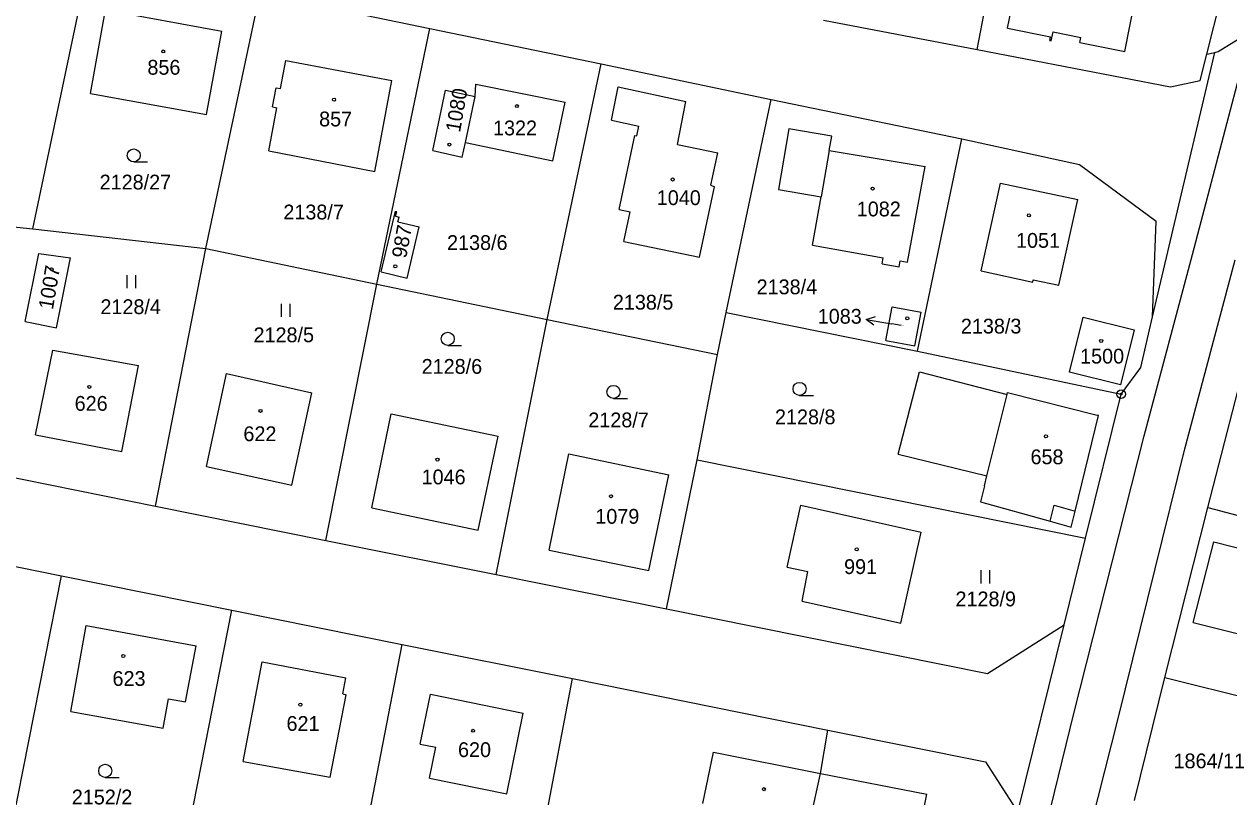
# Model space of a CAD drawing. Extents: x -763205 to -760228, y -1155311 to -1152844.
# Drawn here: x -762054.7 to -761916.2, y -1154656.3 to -1154567.5 of the extents above; entities that cross this region are included whole.
import ezdxf

# ---------------------------------------------------------------- set-up
doc = ezdxf.new("R2010")
doc.units = 0
for name, color, linetype in [('Vrstva 1', 7, 'Continuous'), ('Vrstva 16', 7, 'Continuous'), ('Vrstva 18', 7, 'Continuous'), ('Vrstva 19', 7, 'Continuous'), ('Vrstva 24', 7, 'Continuous'), ('Vrstva 25', 7, 'Continuous'), ('Vrstva 4', 7, 'Continuous')]:
    doc.layers.add(name, color=color, linetype=linetype)

msp = doc.modelspace()

# ---------------------------------------------------------------- linework, layer by layer
at = {"layer": 'Vrstva 1'}
for p, q in [((-761945.16, -1154570.4), (-761942.15, -1154554.69)), ((-761941.67, -1154567.93), (-761939.79, -1154558.64)), ((-761918.77, -1154570.92), (-761915.94, -1154559.73)), ((-762053.67, -1154591.01), (-762047.13, -1154559.9)), ((-761928.21, -1154570.62), (-761926.33, -1154561.22)), ((-762033.79, -1154593.27), (-762027.58, -1154563.92)), ((-762027.58, -1154563.92), (-762008.04, -1154567.96)), ((-762047.05, -1154575.43), (-762045.3, -1154565.83)), ((-762045.3, -1154565.83), (-762031.95, -1154568.28)), ((-762014.14, -1154597.34), (-762008.04, -1154567.96)), ((-762008.04, -1154567.96), (-761988.37, -1154572.04)), ((-761962.8, -1154567), (-761945.16, -1154570.4)), ((-761941.67, -1154567.93), (-761936.72, -1154568.92)), ((-762033.72, -1154577.84), (-762031.95, -1154568.28)), ((-761936.81, -1154569.36), (-761936.72, -1154568.92)), ((-761936.81, -1154569.36), (-761936.64, -1154569.4)), ((-761936.64, -1154569.4), (-761936.44, -1154568.36)), ((-761936.44, -1154568.36), (-761933.24, -1154569)), ((-761933.36, -1154569.59), (-761933.24, -1154569)), ((-761917.45, -1154570.63), (-761913.66, -1154568.26)), ((-761945.16, -1154570.4), (-761922.93, -1154574.67)), ((-761933.36, -1154569.59), (-761928.21, -1154570.62)), ((-761925, -1154601.1), (-761917.85, -1154570.72)), ((-761919.53, -1154573.93), (-761918.77, -1154570.92)), ((-761918.77, -1154570.92), (-761917.85, -1154570.72)), ((-761917.85, -1154570.72), (-761917.45, -1154570.63)), ((-762025.21, -1154574.88), (-762024.6, -1154571.66)), ((-762024.6, -1154571.66), (-762012.4, -1154573.95)), ((-761994.56, -1154601.41), (-761988.37, -1154572.04)), ((-761988.37, -1154572.04), (-761968.83, -1154576.12)), ((-762026.12, -1154576.98), (-762025.71, -1154574.79)), ((-762025.71, -1154574.79), (-762025.21, -1154574.88)), ((-762014.37, -1154584.4), (-762012.4, -1154573.95)), ((-762007.71, -1154582), (-762006.25, -1154575.05)), ((-762006.25, -1154575.05), (-762002.86, -1154575.8)), ((-762002.86, -1154575.8), (-762002.75, -1154574.38)), ((-762002.75, -1154574.38), (-761992.52, -1154576.43)), ((-761987.19, -1154578.49), (-761986.4, -1154574.67)), ((-761986.4, -1154574.67), (-761978.65, -1154576.36)), ((-761922.93, -1154574.67), (-761919.53, -1154573.93)), ((-762047.05, -1154575.43), (-762033.72, -1154577.84)), ((-762003.97, -1154581.06), (-762002.86, -1154575.8)), ((-761993.91, -1154583.16), (-761992.52, -1154576.43)), ((-761979.58, -1154581.31), (-761978.65, -1154576.36)), ((-761973.99, -1154600.62), (-761968.83, -1154576.12)), ((-761968.83, -1154576.12), (-761946.93, -1154580.64)), ((-762026.55, -1154582.03), (-762025.62, -1154577.07)), ((-762026.12, -1154576.98), (-762025.62, -1154577.07)), ((-761987.19, -1154578.49), (-761984.02, -1154579.18)), ((-761984.26, -1154580.32), (-761984.02, -1154579.18)), ((-761986.3, -1154588.77), (-761984.5, -1154580.27)), ((-761984.5, -1154580.27), (-761984.26, -1154580.32)), ((-761966.81, -1154579.49), (-761967.99, -1154586.49)), ((-761961.87, -1154580.33), (-761966.81, -1154579.49)), ((-761962.15, -1154581.99), (-761961.87, -1154580.33)), ((-761952.02, -1154605.04), (-761946.93, -1154580.64)), ((-761946.93, -1154580.64), (-761933.4, -1154583.6)), ((-762007.71, -1154582), (-762004.32, -1154582.75)), ((-762004.32, -1154582.75), (-762003.97, -1154581.06)), ((-762003.97, -1154581.06), (-761993.91, -1154583.16)), ((-761979.58, -1154581.31), (-761974.96, -1154582.24)), ((-761962.15, -1154581.99), (-761951.14, -1154583.83)), ((-762026.55, -1154582.03), (-762014.37, -1154584.4)), ((-761975.75, -1154585.99), (-761974.96, -1154582.24)), ((-761953.16, -1154594.83), (-761951.14, -1154583.83)), ((-761933.4, -1154583.6), (-761924.59, -1154590.1)), ((-761977.07, -1154594.24), (-761975.36, -1154586.15)), ((-761975.75, -1154585.99), (-761975.36, -1154586.15)), ((-761944.7, -1154595.82), (-761942.47, -1154585.73)), ((-761942.47, -1154585.73), (-761933.6, -1154587.63)), ((-761967.99, -1154586.49), (-761963.1, -1154587.31)), ((-761964.09, -1154592.88), (-761963.1, -1154587.31)), ((-761986.3, -1154588.77), (-761985.04, -1154589.04)), ((-761935.78, -1154597.48), (-761933.6, -1154587.63)), ((-762013.65, -1154595.93), (-762012.01, -1154588.97)), ((-762012.01, -1154588.97), (-762011.86, -1154589)), ((-762011.99, -1154589.54), (-762011.86, -1154589)), ((-762011.99, -1154589.54), (-762011.58, -1154589.64)), ((-762011.71, -1154590.18), (-762011.58, -1154589.64)), ((-762011.71, -1154590.18), (-762009.28, -1154590.75)), ((-761985.76, -1154592.44), (-761985.04, -1154589.04)), ((-761925, -1154601.1), (-761924.59, -1154590.1)), ((-762059.87, -1154590.35), (-762053.67, -1154591.01)), ((-762053.67, -1154591.01), (-762033.79, -1154593.27)), ((-762010.65, -1154596.66), (-762009.28, -1154590.75)), ((-761985.76, -1154592.44), (-761977.07, -1154594.24)), ((-761964.09, -1154592.88), (-761955.96, -1154594.32)), ((-762054.56, -1154601.65), (-762052.99, -1154593.83)), ((-762052.99, -1154593.83), (-762049.33, -1154594.31)), ((-762050.95, -1154602.38), (-762049.33, -1154594.31)), ((-762039.58, -1154622.85), (-762033.79, -1154593.27)), ((-762033.79, -1154593.27), (-762014.14, -1154597.34)), ((-761956.08, -1154595.02), (-761955.96, -1154594.32)), ((-761956.08, -1154595.02), (-761954.12, -1154595.37)), ((-761954.12, -1154595.37), (-761954, -1154594.67)), ((-761954, -1154594.67), (-761953.16, -1154594.83)), ((-761944.7, -1154595.82), (-761938.78, -1154597.12)), ((-762013.65, -1154595.93), (-762010.65, -1154596.66)), ((-761938.78, -1154597.12), (-761938.72, -1154596.84)), ((-761938.72, -1154596.84), (-761935.78, -1154597.48)), ((-762020.01, -1154626.79), (-762014.14, -1154597.34)), ((-762014.14, -1154597.34), (-761994.56, -1154601.41)), ((-761955.65, -1154603.83), (-761954.94, -1154599.94)), ((-761954.94, -1154599.94), (-761951.6, -1154600.55)), ((-761974.99, -1154605.42), (-761973.99, -1154600.62)), ((-761973.99, -1154600.62), (-761952.02, -1154605.04)), ((-761952.31, -1154604.44), (-761951.6, -1154600.55)), ((-761934.54, -1154607.46), (-761933, -1154601.16)), ((-761933, -1154601.16), (-761927.12, -1154602.61)), ((-761926.37, -1154606.94), (-761925, -1154601.1)), ((-762054.56, -1154601.65), (-762050.95, -1154602.38)), ((-762000.43, -1154630.73), (-761994.56, -1154601.41)), ((-761994.56, -1154601.41), (-761974.99, -1154605.42)), ((-761927.12, -1154602.61), (-761928.7, -1154608.93)), ((-761955.65, -1154603.83), (-761952.31, -1154604.44)), ((-762053.35, -1154614.66), (-762051.36, -1154604.93)), ((-762051.36, -1154604.93), (-762041.51, -1154606.69)), ((-761977.33, -1154617.54), (-761974.99, -1154605.42)), ((-761952.02, -1154605.04), (-761928.62, -1154609.98)), ((-762043.44, -1154616.56), (-762041.51, -1154606.69)), ((-761928.62, -1154609.98), (-761926.37, -1154606.94)), ((-762033.71, -1154618.29), (-762031.41, -1154607.61)), ((-762031.41, -1154607.61), (-762021.6, -1154609.82)), ((-761954.23, -1154616.89), (-761951.77, -1154607.41)), ((-761951.77, -1154607.41), (-761941.72, -1154610.01)), ((-761928.7, -1154608.93), (-761934.54, -1154607.46)), ((-761918.67, -1154623.02), (-761915.17, -1154609.49)), ((-762023.9, -1154620.43), (-762021.6, -1154609.82)), ((-761941.72, -1154610.01), (-761941.67, -1154609.8)), ((-761941.67, -1154609.8), (-761931.37, -1154612.39)), ((-761932.71, -1154626.54), (-761928.62, -1154609.98)), ((-762014.7, -1154623.04), (-762012.49, -1154612.26)), ((-762012.49, -1154612.26), (-762000.2, -1154614.83)), ((-761933.9, -1154623.42), (-761931.2, -1154612.43)), ((-761931.2, -1154612.43), (-761931.37, -1154612.39)), ((-762053.35, -1154614.66), (-762043.44, -1154616.56)), ((-762002.48, -1154625.63), (-762000.2, -1154614.83)), ((-761994.33, -1154627.92), (-761992.08, -1154616.86)), ((-761992.08, -1154616.86), (-761980.6, -1154619.25)), ((-761980.86, -1154634.67), (-761977.33, -1154617.54)), ((-761977.33, -1154617.54), (-761932.71, -1154626.54)), ((-761954.23, -1154616.89), (-761944.04, -1154619.39)), ((-762059.16, -1154618.91), (-762039.58, -1154622.85)), ((-762033.71, -1154618.29), (-762023.9, -1154620.43)), ((-761982.89, -1154630.25), (-761980.6, -1154619.25)), ((-761944.32, -1154620.51), (-761944.04, -1154619.39)), ((-761944.32, -1154620.51), (-761944.77, -1154622.35)), ((-762039.58, -1154622.85), (-762020.01, -1154626.79)), ((-762014.7, -1154623.04), (-762002.48, -1154625.63)), ((-761967.01, -1154629.85), (-761965.41, -1154622.75)), ((-761965.41, -1154622.75), (-761951.59, -1154625.85)), ((-761944.77, -1154622.35), (-761936.77, -1154624.6)), ((-761934.36, -1154625.27), (-761933.9, -1154623.42)), ((-761923.59, -1154642.54), (-761918.67, -1154623.02)), ((-761918.67, -1154623.02), (-761888.02, -1154630.97)), ((-761936.77, -1154624.6), (-761934.36, -1154625.27)), ((-761953.92, -1154636.32), (-761951.59, -1154625.85)), ((-762020.01, -1154626.79), (-762000.43, -1154630.73)), ((-761935.17, -1154636.49), (-761932.71, -1154626.54)), ((-761920.36, -1154636.24), (-761917.96, -1154626.94)), ((-761917.96, -1154626.94), (-761907.11, -1154629.74)), ((-761994.33, -1154627.92), (-761982.89, -1154630.25)), ((-762058.73, -1154629.19), (-762050.39, -1154630.87)), ((-761967.01, -1154629.85), (-761964.61, -1154630.38)), ((-761965.26, -1154633.79), (-761964.61, -1154630.38)), ((-762056.56, -1154662.09), (-762050.39, -1154630.87)), ((-762050.39, -1154630.87), (-762030.82, -1154634.81)), ((-762000.43, -1154630.73), (-761980.86, -1154634.67)), ((-761965.26, -1154633.79), (-761953.92, -1154636.32)), ((-762036.89, -1154665.87), (-762030.82, -1154634.81)), ((-762030.82, -1154634.81), (-762011.24, -1154638.75)), ((-761980.86, -1154634.67), (-761943.96, -1154642.1)), ((-762049.31, -1154646.47), (-762047.55, -1154636.56)), ((-762047.55, -1154636.56), (-762034.9, -1154638.89)), ((-761943.96, -1154642.1), (-761935.17, -1154636.49)), ((-761940.5, -1154658.03), (-761935.17, -1154636.49)), ((-761920.36, -1154636.24), (-761911.44, -1154638.46)), ((-762017.22, -1154669.66), (-762011.24, -1154638.75)), ((-762011.24, -1154638.75), (-761991.67, -1154642.68)), ((-762036.12, -1154645.36), (-762034.9, -1154638.89)), ((-762029.49, -1154652.18), (-762027.33, -1154640.74)), ((-762027.33, -1154640.74), (-762017.69, -1154642.58)), ((-762018.04, -1154644.42), (-762017.69, -1154642.58)), ((-761997.55, -1154673.44), (-761991.67, -1154642.68)), ((-761991.67, -1154642.68), (-761962.31, -1154648.59)), ((-761927.1, -1154656.68), (-761923.59, -1154642.54)), ((-761923.59, -1154642.54), (-761892.51, -1154650.33)), ((-762038.7, -1154648.37), (-762038.09, -1154645.01)), ((-762038.09, -1154645.01), (-762036.12, -1154645.36)), ((-762019.52, -1154654), (-762017.65, -1154644.52)), ((-762018.04, -1154644.42), (-762017.65, -1154644.52)), ((-762009.15, -1154650.2), (-762007.97, -1154644.47)), ((-762007.97, -1154644.47), (-761997.31, -1154646.65)), ((-762049.31, -1154646.47), (-762038.7, -1154648.37)), ((-761999.2, -1154655.92), (-761997.31, -1154646.65)), ((-761963.18, -1154653.57), (-761962.31, -1154648.59)), ((-761962.31, -1154648.59), (-761944.2, -1154652.24)), ((-762009.15, -1154650.2), (-762007.36, -1154650.57)), ((-762008.08, -1154654.13), (-762007.36, -1154650.57)), ((-761976.69, -1154657.04), (-761975.46, -1154651.12)), ((-761975.46, -1154651.12), (-761963.18, -1154653.57)), ((-762029.49, -1154652.18), (-762019.52, -1154654)), ((-761944.2, -1154652.24), (-761940.5, -1154658.03)), ((-761965.2, -1154663), (-761963.18, -1154653.57)), ((-761963.18, -1154653.57), (-761950.95, -1154655.95)), ((-762008.08, -1154654.13), (-761999.2, -1154655.92)), ((-761952.17, -1154661.88), (-761950.95, -1154655.95))]:
    msp.add_line(p, q, dxfattribs=at)
at = {"layer": 'Vrstva 16'}
for p in [(-761957.914, -1154601.395), (-761953.91, -1154602.11)]:
    msp.add_line(p, (-761954.96, -1154601.92), dxfattribs=at)
msp.add_lwpolyline([(-761957.017, -1154602.063), (-761957.914, -1154601.395), (-761956.842, -1154601.078)], dxfattribs=at)
at = {"layer": 'Vrstva 24'}
for radius in [0.5, 0.1]:
    msp.add_circle((-761928.62, -1154609.98), radius, dxfattribs=at)
at = {"layer": 'Vrstva 25'}
for p, q in [((-762042.08, -1154583.3), (-762040.48, -1154583.3)), ((-762042.82, -1154597.8), (-762042.82, -1154596.3)), ((-762041.82, -1154597.8), (-762041.82, -1154596.3)), ((-762025.11, -1154601.1), (-762025.11, -1154599.6)), ((-762024.11, -1154601.1), (-762024.11, -1154599.6)), ((-762006, -1154604.38), (-762004.4, -1154604.38)), ((-761986.95, -1154610.48), (-761985.35, -1154610.48)), ((-761965.57, -1154610.13), (-761963.97, -1154610.13)), ((-761944.71, -1154631.73), (-761944.71, -1154630.23)), ((-761943.71, -1154631.73), (-761943.71, -1154630.23)), ((-762045.35, -1154654.02), (-762043.75, -1154654.02))]:
    msp.add_line(p, q, dxfattribs=at)
for centre, radius in [((-762038.69, -1154570.61), 0.175), ((-762019.06, -1154576.15), 0.175), ((-761998.05, -1154576.89), 0.175), ((-762042.08, -1154582.55), 0.75), ((-762005.8, -1154581.31), 0.175), ((-761980.15, -1154585.32), 0.175), ((-761957.17, -1154586.36), 0.175), ((-761939.22, -1154589.44), 0.175), ((-762051.51, -1154595.63), 0.175), ((-762012.02, -1154595.3), 0.175), ((-761953.19, -1154601.28), 0.175), ((-762006, -1154603.63), 0.75), ((-761930.91, -1154603.88), 0.175), ((-762047.18, -1154609.15), 0.175), ((-761986.95, -1154609.73), 0.75), ((-761965.57, -1154609.38), 0.75), ((-762027.51, -1154611.91), 0.175), ((-761937.26, -1154614.84), 0.175), ((-762007.17, -1154617.51), 0.175), ((-761987.23, -1154621.72), 0.175), ((-761959, -1154627.82), 0.175), ((-762043.27, -1154640.07), 0.175), ((-762022.93, -1154645.66), 0.175), ((-762003.08, -1154648.67), 0.175), ((-762045.35, -1154653.27), 0.75), ((-761969.67, -1154655.38), 0.175)]:
    msp.add_circle(centre, radius, dxfattribs=at)
at = {"layer": 'Vrstva 4'}
for p, q in [((-761920.42, -1154593.95), (-761913.66, -1154568.26)), ((-761962.15, -1154581.99), (-761963.1, -1154587.31)), ((-761925.97, -1154614.78), (-761920.42, -1154593.95)), ((-761921.29, -1154616.28), (-761915.5, -1154594.54)), ((-761944.04, -1154619.39), (-761941.72, -1154610.01)), ((-761934.06, -1154646.7), (-761925.97, -1154614.78)), ((-761928.97, -1154647.26), (-761921.29, -1154616.28)), ((-761936.77, -1154624.6), (-761936.31, -1154622.75)), ((-761936.31, -1154622.75), (-761933.9, -1154623.42)), ((-761941.46, -1154677), (-761934.06, -1154646.7)), ((-761936.86, -1154678.46), (-761928.97, -1154647.26))]:
    msp.add_line(p, q, dxfattribs=at)

# ---------------------------------------------------------------- texts
at = {"layer": 'Vrstva 16'}
msp.add_text('1083', height=1.7, dxfattribs=at).set_placement((-761963.48, -1154601.89))
at = {"layer": 'Vrstva 18'}
for s, p in [('2128/27', (-762045.993, -1154586.47)), ('2138/7', (-762024.883, -1154589.91)), ('2138/6', (-762006.073, -1154593.42)), ('2138/4', (-761970.503, -1154598.51)), ('2138/5', (-761987.023, -1154600.27)), ('2128/4', (-762045.903, -1154600.79)), ('2138/3', (-761947.033, -1154603.02)), ('2128/5', (-762028.313, -1154604.02)), ('2128/6', (-762008.993, -1154607.65)), ('2128/7', (-761989.843, -1154613.8)), ('2128/8', (-761968.393, -1154613.45)), ('2128/9', (-761947.653, -1154634.37)), ('1864/11', (-761922.597, -1154652.98)), ('2152/2', (-762049.193, -1154657.13))]:
    msp.add_text(s, height=1.7, dxfattribs=at).set_placement(p)
at = {"layer": 'Vrstva 19'}
for s, height, p in [('856', 1.7, (-762040.503, -1154573.28)), ('857', 1.7, (-762020.773, -1154579.22)), ('1322', 1.7, (-762000.79, -1154580.25)), ('1040', 1.7, (-761981.977, -1154588.26)), ('1082', 1.7, (-761958.997, -1154589.56)), ('1051', 1.7, (-761940.697, -1154593.17)), ('1083', 0.1, (-761953.887, -1154602.11)), ('1500', 1.7, (-761933.336, -1154606.47)), ('626', 1.7, (-762048.863, -1154611.9)), ('622', 1.7, (-762029.473, -1154615.39)), ('658', 1.7, (-761939.033, -1154618.04)), ('1046', 1.7, (-762008.997, -1154620.35)), ('1079', 1.7, (-761989.037, -1154624.88)), ('991', 1.7, (-761960.453, -1154630.66)), ('623', 1.7, (-762044.513, -1154643.51)), ('621', 1.7, (-762024.523, -1154648.68)), ('620', 1.7, (-762004.813, -1154651.69))]:
    msp.add_text(s, height=height, dxfattribs=at).set_placement(p)
for s, rotation, p in [('1080', 80.15679, (-762004.583, -1154579.983)), ('987', 79.64113, (-762010.777, -1154594.456)), ('1007', 80.44328, (-762051.365, -1154600.353))]:
    msp.add_text(s, height=1.7, rotation=rotation, dxfattribs=at).set_placement(p)

doc.saveas('drawing.dxf')
